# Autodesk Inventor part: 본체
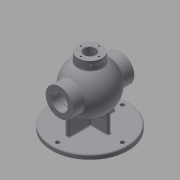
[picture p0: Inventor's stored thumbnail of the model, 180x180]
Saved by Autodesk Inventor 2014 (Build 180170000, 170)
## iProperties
Created: 2020-08
Part Number: 본체
Material: Generic
Document SubType Name: Modeling
Designer: kh
Density: 1 g/cm^3
Appearance: Default
Mass: 648.932 g
Surface Area: 1343.83 cm^2
Volume: 648.932 cm^3
Author: kh
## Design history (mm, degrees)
sketch "Sketch1"
  geometry: C1 r 85 at (0, 0); 1 further point
  constraints: 1 centre point, 1 coincident
  dimensions: "d0" = 170 diameter of C1
extrude "Extrusion1" new body sketch "Sketch1" distance "d1" = 10; taper "d2" = 0 deg
sketch "Sketch3"
  geometry: L1 (-53, 85)-(53, 85); L2 (-53, 85)-(-43, 85); L3 (43, 85)-(53, 85); A1 r 53 centre (0, 85) between (-53, 85) and (53, 85); A2 r 43 centre (0, 85) between (-43, 85) and (43, 85); 1 further point
  constraints: 6 end point, 4 point on circle, 2 centre point, 2 midpoint, 2 point on line, 1 collinear, 1 horizontal, 1 vertical alignment
  dimensions: "d22" = 106 diameter of A1; "d23" = 85 distance of point (0, 0) A1.centre; "d38" = 86 diameter of A2
revolve "Revolution4" sketch "Sketch3" stored, may be unused: angle "d39" = 90 deg
sketch "Sketch4"
  geometry: L1 (-85.514, 85)-(85.514, 85); L2 (-52, 102.5)-(-68, 102.5); L3 (-68, 102.5)-(-68, 116); L4 (-52, 102.5)-(-52, 103.5); L5 (-52, 103.5)-(-50.25, 103.5); L6 (-50.25, 103.5)-(-50.25, 102.5); L7 (68, 102.5)-(68, 116); L8 (-68, 102.5)-(-68, 85); L9 (68, 102.5)-(68, 85); L10 (68, 116)-(29.799, 116); L11 (-29.799, 116)-(-68, 116); L12 (0, 0)-(0, 159.663); L13 (-50.25, 102.5)-(-39.278, 102.5); L14 (39.278, 102.5)-(68, 102.5); C1 r 53 at (0, 85) reference; A1 r 43 centre (0, 85) between (-29.799, 116) and (-39.278, 102.5) reference; A2 r 43 centre (0, 85) between (29.799, 116) and (-29.799, 116); A3 r 43 centre (0, 85) between (39.278, 102.5) and (-39.278, 102.5); 2 further points
  constraints: 28 end point, 7 perpendicular, 7 point on circle, 6 parallel, 3 coincident, 3 collinear, 2 centre point, 2 point on line, 1 horizontal, 1 midpoint, 1 vertical alignment, 1 other
  dimensions: "d27" = 136 distance between parallel lines of L7 L3; "d29" = 16 distance of L2.start L2.end; "d30" = 1.75 distance of L4.end L5.end; "d31" = 37 diameter of L5 L1; "d41" = 62 diameter of L10 L1; "d42" = 35 diameter of L14 L1
revolve "Revolution2" stored, may be unused: angle "d32" = 90 deg
workplane "Work Plane1"
sketch "Sketch5"
  geometry: C1 r 27 at (0, 0); 1 further point
  constraints: 1 centre point, 1 coincident
  dimensions: "d35" = 54 diameter of C1
extrude "Extrusion2" join sketch "Sketch5" stored distance "d36" = 10; taper "d37" = 0 deg
revolve "Revolution5" stored, may be unused: angle "d43" = 90 deg
hole "Hole1" diameter "d46" = 26; stored, may be unused: countersink angle "d50" = 90 deg, drill point angle "d52" = 118 deg; dims "d44" = 10, "d45" = 10, "d47" = 6, "d48" = 4, "d49" = 2, "d51" = 8
chamfer "Chamfer1" distance "d53" = 1; stored, may be unused: second distance "d54" = 2, angle "d55" = 45 deg
sketch "Sketch6"
  geometry: C1 r 27 at (0, 0) reference; 2 further points
  constraints: 1 vertical alignment
  dimensions: "d56" = 20 distance of point (0, 20) point (0, 0)
hole "Hole2" sketch "Sketch6" at (0, 20) diameter "d57" = 3.459; stored, may be unused: countersink angle "d61" = 90 deg, drill point angle "d63" = 118 deg; dims "d58" = 12, "d59" = 4, "d60" = 2, "d62" = 15
pattern_circular "Circular Pattern1" dims angle "d65" = 360 deg
sketch "Sketch7"
  geometry: C1 r 31 at (0, 0) reference; 2 further points
  constraints: 1 vertical alignment
  dimensions: "d67" = 24 distance of C1.centre point (0, 24)
hole "Hole3" sketch "Sketch7" at (0, 24) diameter "d68" = 3.459; stored, may be unused: countersink angle "d72" = 90 deg, drill point angle "d74" = 118 deg; dims "d69" = 12, "d70" = 4, "d71" = 2, "d73" = 15
pattern_circular "Circular Pattern2" dims angle "d76" = 360 deg
mirror "Mirror1"
sketch "Sketch8"
  geometry: L1 (4, -52)-(-4, -52); L2 (-4, -52)-(-4, 52); L3 (-4, 52)-(4, 52); L4 (4, 52)-(4, -52); L5 (4, -52)-(-4, 52); L6 (-4, -52)-(4, 52); L7 (-43, -4)-(43, -4); L8 (43, -4)-(43, 4); L9 (43, 4)-(-43, 4); L10 (-43, 4)-(-43, -4); L11 (-43, -4)-(43, 4); L12 (43, -4)-(-43, 4); 1 further point
  constraints: 24 end point, 4 midpoint, 4 parallel, 2 horizontal, 2 perpendicular
  dimensions: "d78" = 8 distance of L7.end L8.end; "d79" = 8 distance of L2.end L3.end; "d80" = 86 distance of L7.start L7.end; "d81" = 104 distance of L3.end L1.start
extrude "Extrusion3" join sketch "Sketch8" stored distance "d82" = 10; taper "d83" = 0 deg
fillet "Fillet1" dims "d84" = 3
fillet "Fillet2" dims "d85" = 3
workplane "Work Plane2"
sketch "Sketch9"
  geometry: L1 (-20.739, -5.998)-(20.739, -5.998); L2 (20.739, -5.998)-(20.739, -12.002); L3 (20.739, -12.002)-(-20.739, -12.002); L4 (-20.739, -12.002)-(-20.739, -5.998); L5 (-20.739, -5.998)-(20.739, -12.002); L6 (-27, 0)-(-27, -17.714) reference; L7 (-27, 0)-(27, 0) reference; 2 further points
  constraints: 2 end point, 1 midpoint, 2 other
  dimensions: "d86" = 27 distance from line of point (0, -9) L6; "d87" = 9 distance from line of point (0, -9) L7
emboss "Emboss1" sketch "Sketch9" dims "d1" = 10, "d2" = 0, "d88" = 0.5, "d89" = 0
sketch "Sketch10"
  geometry: 2 further points
  constraints: 1 vertical alignment
  dimensions: "d90" = 72.5 distance of point (0, 0) point (0, 72.5)
hole "Hole4" sketch "Sketch10" at (0, 72.5) diameter "d91" = 9; stored, may be unused: countersink angle "d95" = 90 deg, drill point angle "d97" = 118 deg; dims "d92" = 12, "d93" = 4, "d94" = 2, "d96" = 15
pattern_circular "Circular Pattern3" dims angle "d99" = 360 deg
body "Solid1"
other parameters: "d26" = 35, "d28" = 62
